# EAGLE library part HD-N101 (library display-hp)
LED DISPLAY 1-character 7 segment, decimal point right
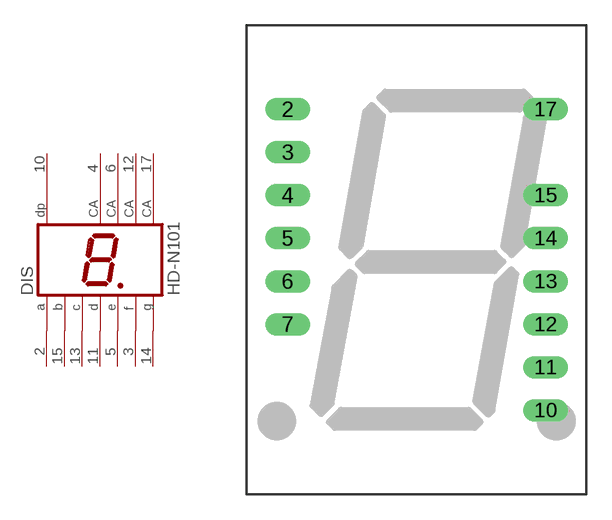
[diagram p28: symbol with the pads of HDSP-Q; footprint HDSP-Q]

Designator prefix DIS

## HD-N101 (OC_FARNELL: unknown; OC_NEWARK: unknown)  [HDSP-Q]
2  A  pas
3  F  pas
4  CA  pas
5  E  pas
6  CA  pas
10  DP  pas
11  D  pas
12  CA  pas
13  C  pas
14  G  pas
15  B  pas
17  CA  pas

## Footprint HDSP-Q (pad centres in mm)
LED DISPLAY 20-mm 1 character 7 segment, 2 decimal points
drill 0.813 long: 2 -7.62,8.89; 3 -7.62,6.35; 4 -7.62,3.81; 5 -7.62,1.27; 6 -7.62,-1.27; 7 -7.62,-3.81; 10 7.62,-8.89; 11 7.62,-6.35; 12 7.62,-3.81; 13 7.62,-1.27; 14 7.62,1.27; 15 7.62,3.81; 17 7.62,8.89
